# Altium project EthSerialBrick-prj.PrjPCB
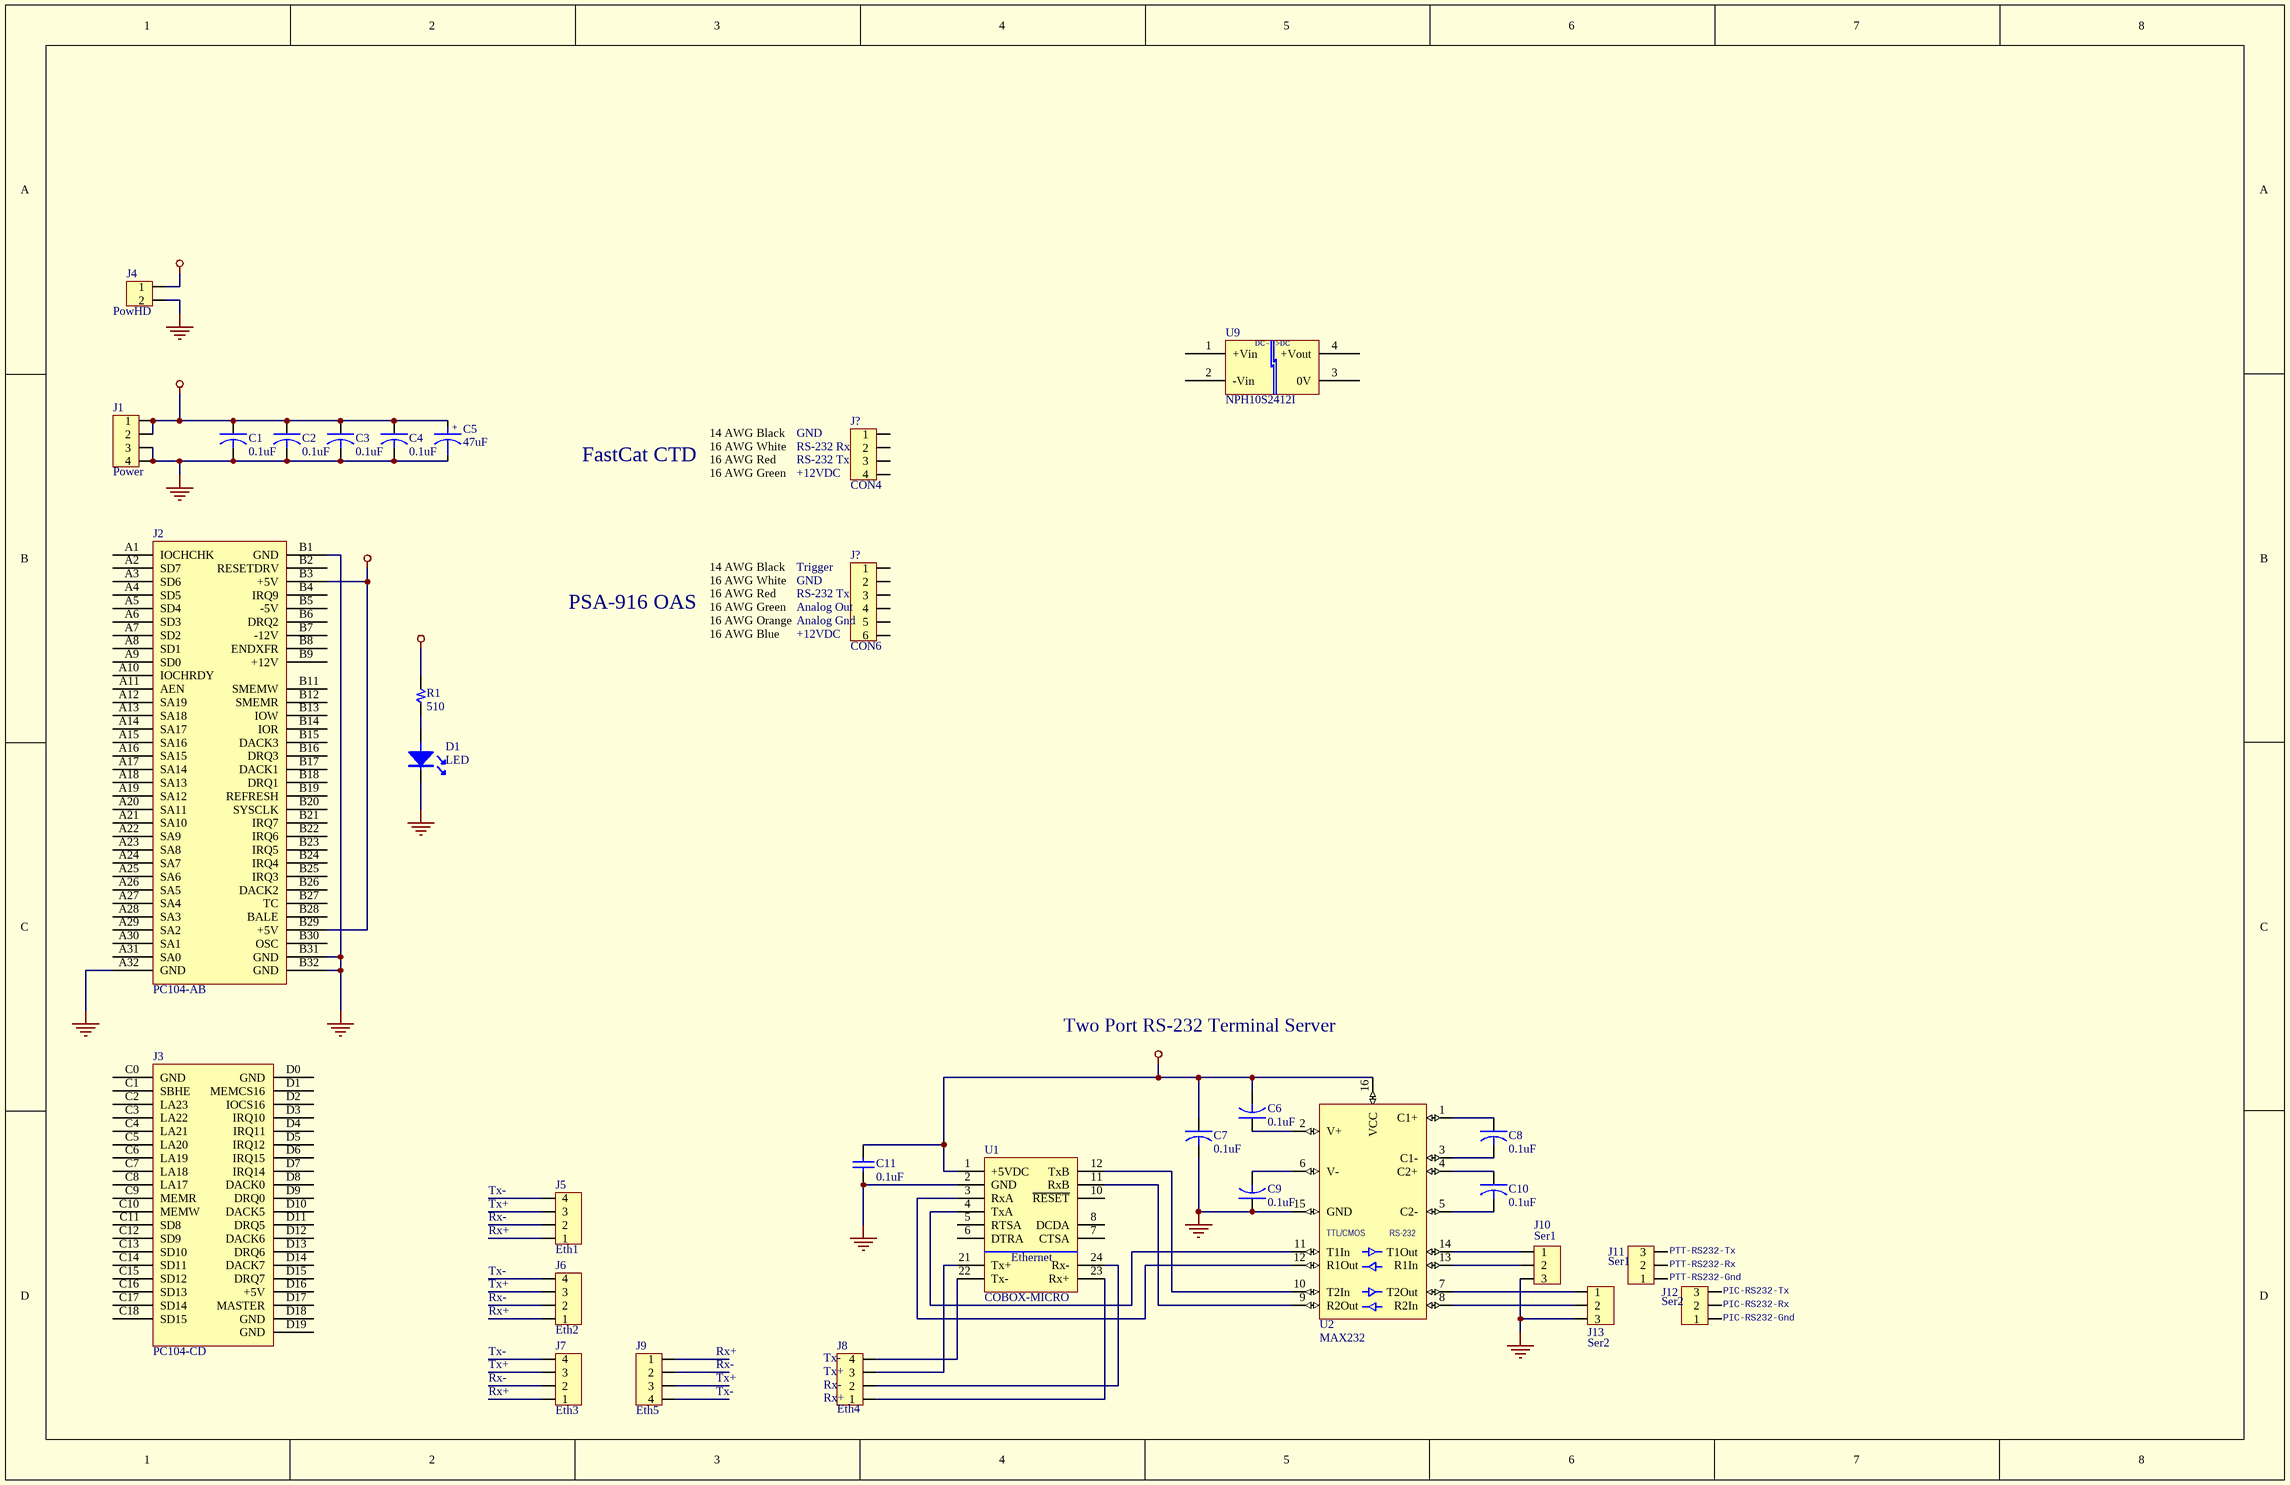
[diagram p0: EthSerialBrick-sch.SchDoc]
1 sheet, 31 parts. Net scope: global (net labels, ports and power ports of the same name join across sheets).
Board file: EthSerialBrick-pcb.PcbDoc

## Sheet EthSerialBrick-sch.SchDoc: Ethernet to Serial Brick for Mapping AUV Nose
size Tabloid; Organization: Monterey Bay Aquarium Research Institute; Address1: 7700 Sandholdt Rd; Address2: Moss Landing, CA 95039-9644; Revision: 1; SheetNumber: 1; SheetTotal: 1; CompanyName: MBARI; Engineer: Mark Sibenac

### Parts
(Parts that share a designator on the sheet are numbered #1, #2 ... from top to bottom, then left to right.)
C1  0.1uF  [1206]
C2  0.1uF  [1206]
C3  0.1uF  [1206]
C4  0.1uF  [1206]
C5  47uF  [6032POL]
C6  0.1uF  [1206]
C7  0.1uF  [1206]
C8  0.1uF  [1206]
C9  0.1uF  [1206]
C10  0.1uF  [1206]
C11  0.1uF  [RAD0.1]
D1  LED  [SOT-23]
J1  Power  [SIP4]
J2  PC104-AB  [PC104-AB]
J3  PC104-CD  [PC104-CD]
J4  PowHD  [SIP2]
J5  Eth1  [SIP4]
J6  Eth2  [SIP4]
J7  Eth3  [SIP4]
J8  Eth4  [SIP4]
J9  Eth5  [SIP4]
J10  Ser1  [CGRID3]
J11  Ser1  [CGRID3-RA]  (mechanical)
J12  Ser2  [CGRID3-RA]  (mechanical)
J13  Ser2  [CGRID3]
J?#1  CON4  [SIP4]
J?#2  CON6  [SIP6]
R1  510  [1206]
U1  COBOX-MICRO  [COBOX-MICRO]
U2  MAX232  [SOIC-16-0.15W]
U9  NPH10S2412I  [NPH10S]

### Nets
GND: C1.2 C2.2 C3.2 C4.2 C5.2 C7.2 C9.1 C11.1 D1.3(K) J1.3 J1.4 J2.A32(GND) J2.B1(GND) J2.B31(GND) J2.B32(GND) J4.2 J10.3 J13.3 U1.2(GND) U2.15(GND)
VCC: C1.1 C2.1 C3.1 C4.1 C5.1 C6.2 C7.1 C11.2 J1.1 J1.2 J2.B3(+5V) J2.B29(+5V) J4.1 R1.1 U1.1(+5VDC) U2.16(VCC)
NetC6_1: C6.1 U2.2(V+)
NetC8_1: C8.1 U2.1(C1+)
NetC8_2: C8.2 U2.3(C1-)
NetC9_2: C9.2 U2.6(V-)
NetC10_1: C10.1 U2.4(C2+)
NetC10_2: C10.2 U2.5(C2-)
NetD1_2: D1.2(A) R1.2
NetJ8_1: J8.1 U1.23(Rx+)
NetJ8_2: J8.2 U1.24(Rx-)
NetJ8_3: J8.3 U1.21(Tx+)
NetJ8_4: J8.4 U1.22(Tx-)
NetJ10_1: J10.1 U2.14(T1Out)
NetJ10_2: J10.2 U2.13(R1In)
NetJ13_1: J13.1 U2.7(T2Out)
NetJ13_2: J13.2 U2.8(R2In)
NetU1_3: U1.3(RxA) U2.12(R1Out)
NetU1_4: U1.4(TxA) U2.11(T1In)
NetU1_11: U1.11(RxB) U2.9(R2Out)
NetU1_12: U1.12(TxB) U2.10(T2In)

Not connected (* = marked no-connect by the designer): J2 A1(IOCHCHK) A2(SD7) A3(SD6) A4(SD5) A5(SD4) A6(SD3) A7(SD2) A8(SD1) A9(SD0) A10(IOCHRDY) A11(AEN) A12(SA19) A13(SA18) A14(SA17) A15(SA16) A16(SA15) A17(SA14) A18(SA13) A19(SA12) A20(SA11) A21(SA10) A22(SA9) A23(SA8) A24(SA7) A25(SA6) A26(SA5) A27(SA4) A28(SA3) A29(SA2) A30(SA1) A31(SA0) B2(RESETDRV) B4(IRQ9) B5(-5V) B6(DRQ2) B7(-12V) B8(ENDXFR) B9(+12V) B10(KEY) B11(SMEMW) B12(SMEMR) B13(IOW) B14(IOR) B15(DACK3) B16(DRQ3) B17(DACK1) B18(DRQ1) B19(REFRESH) B20(SYSCLK) B21(IRQ7) B22(IRQ6) B23(IRQ5) B24(IRQ4) B25(IRQ3) B26(DACK2) B27(TC) B28(BALE) B30(OSC); J3 C0(GND) C1(SBHE) C2(LA23) C3(LA22) C4(LA21) C5(LA20) C6(LA19) C7(LA18) C8(LA17) C9(MEMR) C10(MEMW) C11(SD8) C12(SD9) C13(SD10) C14(SD11) C15(SD12) C16(SD13) C17(SD14) C18(SD15) C19(KEY) D0(GND) D1(MEMCS16) D2(IOCS16) D3(IRQ10) D4(IRQ11) D5(IRQ12) D6(IRQ15) D7(IRQ14) D8(DACK0) D9(DRQ0) D10(DACK5) D11(DRQ5) D12(DACK6) D13(DRQ6) D14(DACK7) D15(DRQ7) D16(+5V) D17(MASTER) D18(GND) D19(GND); J5 1 2 3 4; J6 1 2 3 4; J7 1 2 3 4; J9 1 2 3 4; J11 1 2 3; J12 1 2 3; J?#1 1 2 3 4; J?#2 1 2 3 4 5 6; U1 5(RTSA) 6(DTRA) 7(CTSA) 8(DCDA) 10(~{RESET}); U9 1(+Vin) 2(-Vin) 3(0V) 4(+Vout)

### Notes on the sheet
- 14 AWG
- Black
- GND
- FastCat CTD
- 16 AWG
- White
- Red
- Green
- (near J?#1) RS-232 Rx
- (near J?#1) RS-232 Tx
- (near J?#1) +12VDC
- (near J?#2) Trigger
- PSA-916 OAS
- Orange
- (near J?#2) RS-232 Tx
- (near J?#2) Analog Out
- (near J?#2) Analog Gnd
- Blue
- (near J?#2) +12VDC
- Two Port RS-232 Terminal Server
- (near J5) Tx-
- (near J5) Tx+
- Rx-
- Rx+
- Tx-
- Tx+
- (near J11) PTT-RS232-Tx
- PTT-RS232-Rx
- PTT-RS232-Gnd
- (near J12) PIC-RS232-Rx
- (near J12) PIC-RS232-Tx
- (near J8) Tx-
- (near J8) Tx+
- (near J12) PIC-RS232-Gnd
- (near J7) Rx+
- (near J8) Rx-
- (near J8) Rx+

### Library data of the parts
C1-C4 = CAPACITOR: ManufPartNo: C1206C104K5RACTU; Manufacturer: Kemet; VendorPartNo: 399-1249-1-ND; Cost/ea: 0.121; Reference: T032, 738; Vendor: Digi-Key
C5 = CAPACITOR POL: Capacitor; ManufPartNo: T494C476K010AS; Manufacturer: Kemet; VendorPartNo: 399-1776-1-ND; Cost/ea: 1.46; Reference: T032, 690; Vendor: Digi-Key
C6-C10 = CAPACITOR: ManufPartNo: C1206C104J5RACTU; Manufacturer: Kemet; VendorPartNo: 399-1250-1-ND; Cost/ea: 0.253; Reference: T033, 785; Vendor: Digi-Key
C11 = Cap: Capacitor; Manufacturer: BC Components; ManufPartNo: K104K15X7RF5TL2; VendorPartNo: BC1084CT-ND; Cost/ea: .14; Reference: pg. 680, T031; Vendor: Digi-Key
D1 = LED: ManufPartNo: SML-LX15USBC-TR; Manufacturer: Lumex; VendorPartNo: 67-1668-1-ND; Cost/ea: 3.13; Reference: T032, 1138; Vendor: Digi-Key
J1 J?#1 = CON4: Connector
J2 = PC104-AB: PC/104 A&B rails; ManufPartNo: 1185CP-104G; Manufacturer: CommCon
J3 = PC104-CD: PC/104 C&D rails
J4 = CON2: Connector
J5-J9 = CON4: Connector 4 pin
J10 J13 = CON3: Connector; ManufPartNo: 70543-0002; Manufacturer: Molex; VendorPartNo: WM4801-ND; Cost/ea: 0.89; Reference: T033, 94; Vendor: Digi-Key
J11 J12 = CON3: Connector; Manufacturer: Molex; VendorPartNo: WM2901-ND; Cost/ea: .599; Reference: pg. 77, T031; Vendor: Digi-Key
J?#2 = CON6: Connector
R1 = RESISTOR: ManufPartNo: 9C12063A0510JLHFT; Manufacturer: Yageo; VendorPartNo: 311-510ECT-ND; Cost/ea: .097; Reference: T032, 754; Vendor: Digi-Key
U1 = COBOX-MICRO: CoBox Micro Terminal Server; ManufPartNo: CO-E2-11AA; Manufacturer: Lantronix; Cost/ea: 67.00; Vendor: Symmetry Electronics
U2 = MAX232: MAX232 Communications Chip; ManufPartNo: MAX232ACSE; Manufacturer: Maxim; VendorPartNo: MAX232ACSE-ND; Cost/ea: 5.51; Reference: T033, 483; Vendor: Digi-Key
U9 = NPH10S: DC->DC Isol Converter 10W; Manufacturer: C&D Technologies; VendorPartNo: 580-NPH10S2412I; Cost/ea: 36.18; Reference: pg.853; Vendor: Mouser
